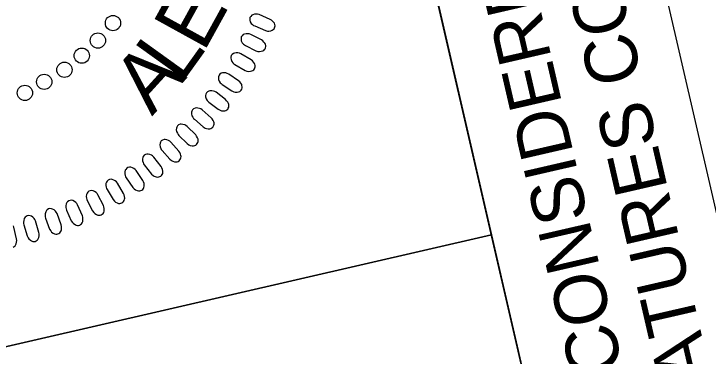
# Model space of a CAD drawing. Extents: x 480532 to 481977, y 491295 to 493182.
# Drawn here: x 480676.5 to 480749.4, y 492847.7 to 492883.6 of the extents above; entities that cross this region are included whole.
import ezdxf

# ---------------------------------------------------------------- set-up
doc = ezdxf.new("R2010")
doc.units = 0
for name, color, linetype in [('Sheet PE Seal Cell', 7, 'Continuous'), ('Sheet Plan CELL', 7, 'Continuous'), ('Sheet Sticker Exception Certification CELL', 7, 'Continuous'), ('Sheet Sticker Incomplete CELL', 7, 'Continuous')]:
    doc.layers.add(name, color=color, linetype=linetype)

msp = doc.modelspace()

# ---------------------------------------------------------------- linework, layer by layer
at = {"layer": 'Sheet PE Seal Cell'}
for points in [[(480701.799, 492882.305), (480702.928, 492881.825), (480703.144, 492881.774), (480703.293, 492881.767), (480703.494, 492881.804), (480703.633, 492881.851), (480703.75, 492881.923), (480703.827, 492882.003), (480703.89, 492882.099), (480703.915, 492882.209), (480703.934, 492882.331), (480703.921, 492882.451), (480703.869, 492882.586), (480703.82, 492882.672), (480703.708, 492882.793), (480703.566, 492882.918), (480703.428, 492883.001), (480702.275, 492883.5), (480702.11, 492883.546), (480701.964, 492883.559), (480701.782, 492883.539), (480701.609, 492883.491), (480701.498, 492883.432), (480701.381, 492883.311), (480701.304, 492883.181), (480701.283, 492883.028), (480701.288, 492882.912), (480701.329, 492882.756), (480701.439, 492882.58), (480701.578, 492882.448), (480701.686, 492882.369)], [(480700.834, 492880.255), (480701.931, 492879.705), (480702.144, 492879.64), (480702.292, 492879.624), (480702.494, 492879.648), (480702.635, 492879.686), (480702.757, 492879.75), (480702.84, 492879.826), (480702.908, 492879.918), (480702.94, 492880.026), (480702.967, 492880.147), (480702.96, 492880.267), (480702.918, 492880.406), (480702.874, 492880.495), (480702.77, 492880.622), (480702.637, 492880.756), (480702.504, 492880.848), (480701.384, 492881.417), (480701.222, 492881.473), (480701.077, 492881.495), (480700.895, 492881.487), (480700.72, 492881.45), (480700.604, 492881.398), (480700.481, 492881.285), (480700.396, 492881.16), (480700.365, 492881.009), (480700.363, 492880.892), (480700.394, 492880.734), (480700.492, 492880.552), (480700.623, 492880.41), (480700.725, 492880.326)], [(480699.723, 492878.265), (480700.783, 492877.647), (480700.991, 492877.568), (480701.138, 492877.543), (480701.341, 492877.555), (480701.485, 492877.583), (480701.61, 492877.64), (480701.697, 492877.71), (480701.771, 492877.797), (480701.81, 492877.904), (480701.844, 492878.023), (480701.846, 492878.143), (480701.812, 492878.284), (480701.773, 492878.375), (480701.678, 492878.51), (480701.553, 492878.651), (480701.426, 492878.751), (480700.344, 492879.39), (480700.187, 492879.456), (480700.043, 492879.487), (480699.86, 492879.491), (480699.684, 492879.464), (480699.566, 492879.42), (480699.435, 492879.315), (480699.342, 492879.195), (480699.301, 492879.046), (480699.292, 492878.931), (480699.313, 492878.771), (480699.4, 492878.582), (480699.521, 492878.433), (480699.618, 492878.342)], [(480698.38, 492876.174), (480699.399, 492875.491), (480699.601, 492875.4), (480699.746, 492875.365), (480699.95, 492875.364), (480700.095, 492875.384), (480700.224, 492875.432), (480700.316, 492875.497), (480700.394, 492875.579), (480700.44, 492875.684), (480700.482, 492875.8), (480700.491, 492875.919), (480700.466, 492876.062), (480700.433, 492876.156), (480700.346, 492876.296), (480700.23, 492876.445), (480700.111, 492876.553), (480699.071, 492877.258), (480698.917, 492877.334), (480698.776, 492877.374), (480698.594, 492877.389), (480698.416, 492877.374), (480698.296, 492877.337), (480698.158, 492877.24), (480698.058, 492877.127), (480698.008, 492876.981), (480697.992, 492876.866), (480698.003, 492876.705), (480698.078, 492876.511), (480698.19, 492876.355), (480698.281, 492876.259)], [(480696.994, 492874.305), (480697.968, 492873.559), (480698.164, 492873.455), (480698.307, 492873.412), (480698.51, 492873.398), (480698.656, 492873.408), (480698.787, 492873.449), (480698.883, 492873.507), (480698.967, 492873.585), (480699.019, 492873.686), (480699.068, 492873.799), (480699.084, 492873.918), (480699.068, 492874.062), (480699.042, 492874.158), (480698.964, 492874.303), (480698.857, 492874.459), (480698.745, 492874.574), (480697.751, 492875.344), (480697.603, 492875.429), (480697.465, 492875.478), (480697.284, 492875.504), (480697.105, 492875.5), (480696.982, 492875.471), (480696.839, 492875.383), (480696.733, 492875.276), (480696.674, 492875.133), (480696.65, 492875.02), (480696.651, 492874.858), (480696.713, 492874.66), (480696.815, 492874.497), (480696.9, 492874.395)], [(480695.475, 492872.515), (480696.401, 492871.709), (480696.591, 492871.593), (480696.73, 492871.54), (480696.932, 492871.514), (480697.079, 492871.515), (480697.212, 492871.548), (480697.311, 492871.6), (480697.4, 492871.672), (480697.458, 492871.769), (480697.514, 492871.879), (480697.538, 492871.998), (480697.531, 492872.142), (480697.51, 492872.24), (480697.442, 492872.389), (480697.346, 492872.551), (480697.241, 492872.673), (480696.297, 492873.503), (480696.154, 492873.598), (480696.02, 492873.656), (480695.841, 492873.693), (480695.662, 492873.7), (480695.538, 492873.679), (480695.389, 492873.6), (480695.276, 492873.5), (480695.208, 492873.361), (480695.177, 492873.25), (480695.168, 492873.088), (480695.218, 492872.887), (480695.31, 492872.718), (480695.387, 492872.611)], [(480693.838, 492870.827), (480694.711, 492869.965), (480694.893, 492869.837), (480695.029, 492869.776), (480695.229, 492869.737), (480695.375, 492869.729), (480695.511, 492869.753), (480695.612, 492869.799), (480695.705, 492869.865), (480695.77, 492869.959), (480695.832, 492870.065), (480695.864, 492870.182), (480695.866, 492870.326), (480695.851, 492870.424), (480695.792, 492870.578), (480695.706, 492870.746), (480695.609, 492870.874), (480694.72, 492871.763), (480694.584, 492871.866), (480694.452, 492871.932), (480694.276, 492871.98), (480694.098, 492871.999), (480693.973, 492871.986), (480693.82, 492871.916), (480693.701, 492871.823), (480693.624, 492871.689), (480693.586, 492871.58), (480693.568, 492871.419), (480693.604, 492871.215), (480693.685, 492871.04), (480693.756, 492870.929)], [(480692.076, 492869.234), (480692.893, 492868.319), (480693.067, 492868.181), (480693.199, 492868.111), (480693.395, 492868.059), (480693.542, 492868.042), (480693.678, 492868.057), (480693.782, 492868.097), (480693.879, 492868.157), (480693.949, 492868.247), (480694.019, 492868.349), (480694.057, 492868.463), (480694.068, 492868.607), (480694.06, 492868.706), (480694.011, 492868.863), (480693.936, 492869.036), (480693.847, 492869.171), (480693.015, 492870.113), (480692.885, 492870.224), (480692.758, 492870.298), (480692.586, 492870.358), (480692.409, 492870.387), (480692.283, 492870.382), (480692.127, 492870.322), (480692.001, 492870.237), (480691.917, 492870.108), (480691.872, 492870.001), (480691.843, 492869.842), (480691.867, 492869.636), (480691.937, 492869.457), (480692.001, 492869.341)], [(480690.217, 492867.731), (480690.975, 492866.766), (480691.14, 492866.617), (480691.268, 492866.539), (480691.461, 492866.476), (480691.605, 492866.449), (480691.743, 492866.456), (480691.849, 492866.489), (480691.95, 492866.543), (480692.025, 492866.628), (480692.101, 492866.725), (480692.146, 492866.837), (480692.167, 492866.98), (480692.165, 492867.08), (480692.125, 492867.239), (480692.061, 492867.417), (480691.98, 492867.556), (480691.21, 492868.549), (480691.087, 492868.668), (480690.966, 492868.75), (480690.797, 492868.82), (480690.622, 492868.862), (480690.496, 492868.864), (480690.336, 492868.814), (480690.206, 492868.737), (480690.114, 492868.613), (480690.062, 492868.509), (480690.023, 492868.352), (480690.035, 492868.146), (480690.092, 492867.962), (480690.149, 492867.842)], [(480688.315, 492866.369), (480689.011, 492865.359), (480689.167, 492865.199), (480689.289, 492865.114), (480689.477, 492865.038), (480689.62, 492865.003), (480689.757, 492865.001), (480689.865, 492865.027), (480689.97, 492865.074), (480690.05, 492865.154), (480690.132, 492865.247), (480690.184, 492865.355), (480690.213, 492865.497), (480690.218, 492865.596), (480690.188, 492865.758), (480690.135, 492865.939), (480690.064, 492866.084), (480689.357, 492867.123), (480689.242, 492867.25), (480689.126, 492867.339), (480688.962, 492867.42), (480688.79, 492867.471), (480688.665, 492867.482), (480688.502, 492867.442), (480688.367, 492867.373), (480688.267, 492867.256), (480688.209, 492867.155), (480688.16, 492867.001), (480688.159, 492866.794), (480688.205, 492866.608), (480688.254, 492866.484)], [(480686.306, 492865.127), (480686.937, 492864.076), (480687.082, 492863.907), (480687.198, 492863.813), (480687.382, 492863.726), (480687.522, 492863.682), (480687.659, 492863.671), (480687.769, 492863.691), (480687.875, 492863.731), (480687.961, 492863.806), (480688.048, 492863.893), (480688.107, 492863.998), (480688.145, 492864.138), (480688.156, 492864.237), (480688.137, 492864.4), (480688.095, 492864.585), (480688.033, 492864.733), (480687.393, 492865.814), (480687.286, 492865.948), (480687.176, 492866.045), (480687.017, 492866.135), (480686.849, 492866.197), (480686.724, 492866.216), (480686.559, 492866.186), (480686.42, 492866.126), (480686.313, 492866.015), (480686.249, 492865.919), (480686.191, 492865.768), (480686.176, 492865.561), (480686.21, 492865.373), (480686.252, 492865.246)], [(480684.227, 492863.977), (480684.791, 492862.888), (480684.925, 492862.71), (480685.035, 492862.61), (480685.213, 492862.511), (480685.35, 492862.458), (480685.486, 492862.439), (480685.597, 492862.452), (480685.706, 492862.486), (480685.796, 492862.555), (480685.888, 492862.636), (480685.954, 492862.737), (480686.001, 492862.874), (480686.018, 492862.973), (480686.009, 492863.136), (480685.979, 492863.323), (480685.926, 492863.475), (480685.355, 492864.595), (480685.257, 492864.735), (480685.153, 492864.838), (480685, 492864.939), (480684.837, 492865.011), (480684.714, 492865.037), (480684.546, 492865.018), (480684.404, 492864.967), (480684.29, 492864.863), (480684.22, 492864.771), (480684.153, 492864.624), (480684.125, 492864.419), (480684.147, 492864.228), (480684.181, 492864.099)], [(480682.053, 492862.984), (480682.548, 492861.861), (480682.67, 492861.675), (480682.774, 492861.569), (480682.946, 492861.459), (480683.079, 492861.397), (480683.213, 492861.37), (480683.325, 492861.375), (480683.436, 492861.402), (480683.53, 492861.466), (480683.627, 492861.541), (480683.699, 492861.638), (480683.755, 492861.772), (480683.778, 492861.869), (480683.779, 492862.033), (480683.761, 492862.221), (480683.718, 492862.376), (480683.218, 492863.529), (480683.129, 492863.675), (480683.032, 492863.785), (480682.886, 492863.895), (480682.726, 492863.978), (480682.605, 492864.012), (480682.438, 492864.003), (480682.292, 492863.961), (480682.172, 492863.864), (480682.096, 492863.777), (480682.02, 492863.634), (480681.979, 492863.431), (480681.99, 492863.239), (480682.015, 492863.109)], [(480679.862, 492862.137), (480680.285, 492860.985), (480680.396, 492860.793), (480680.493, 492860.679), (480680.657, 492860.558), (480680.786, 492860.489), (480680.919, 492860.453), (480681.03, 492860.452), (480681.143, 492860.471), (480681.241, 492860.529), (480681.343, 492860.598), (480681.421, 492860.69), (480681.484, 492860.82), (480681.513, 492860.916), (480681.525, 492861.079), (480681.519, 492861.268), (480681.485, 492861.426), (480681.059, 492862.608), (480680.98, 492862.759), (480680.889, 492862.875), (480680.75, 492862.994), (480680.597, 492863.086), (480680.478, 492863.128), (480680.31, 492863.13), (480680.163, 492863.097), (480680.036, 492863.008), (480679.955, 492862.925), (480679.87, 492862.788), (480679.816, 492862.588), (480679.815, 492862.396), (480679.832, 492862.264)], [(480677.579, 492861.442), (480677.928, 492860.265), (480678.027, 492860.066), (480678.117, 492859.947), (480678.273, 492859.816), (480678.397, 492859.738), (480678.528, 492859.694), (480678.639, 492859.686), (480678.753, 492859.699), (480678.854, 492859.75), (480678.96, 492859.813), (480679.043, 492859.9), (480679.115, 492860.025), (480679.15, 492860.119), (480679.171, 492860.281), (480679.178, 492860.471), (480679.154, 492860.629), (480678.803, 492861.837), (480678.733, 492861.993), (480678.65, 492862.113), (480678.518, 492862.241), (480678.371, 492862.343), (480678.256, 492862.392), (480678.088, 492862.405), (480677.939, 492862.381), (480677.807, 492862.3), (480677.721, 492862.222), (480677.628, 492862.09), (480677.561, 492861.894), (480677.548, 492861.702), (480677.556, 492861.57)]]:
    msp.add_lwpolyline(points, close=True, dxfattribs=at)
msp.add_lwpolyline([(480676.459, 492859.093), (480676.57, 492859.149), (480676.658, 492859.23), (480676.738, 492859.351), (480676.778, 492859.442), (480676.81, 492859.603), (480676.828, 492859.792), (480676.814, 492859.952), (480676.54, 492861.179), (480676.48, 492861.338)], dxfattribs=at)
for centre in [(480686.93, 492882.614), (480685.349, 492880.779), (480683.659, 492879.19), (480681.834, 492877.708), (480679.713, 492876.443), (480677.691, 492875.283)]:
    msp.add_circle(centre, 0.801, dxfattribs=at)
at = {"layer": 'Sheet Plan CELL'}
msp.add_line((480617.018, 492835.113), (480726.604, 492860.388), dxfattribs=at)
for points in [[(481918.067, 491698.303), (480894.93, 491462.423), (480602.878, 492729.179), (480749.103, 492762.9), (480704.18, 492957.828), (481581.119, 493159.981)], [(480617.018, 492835.113), (480594.546, 492932.542), (480704.18, 492957.828), (480726.655, 492860.387)], [(480639.493, 492737.62), (480617.018, 492835.113), (480726.655, 492860.387), (480749.103, 492762.9)]]:
    msp.add_lwpolyline(points, close=True, dxfattribs=at)
at = {"layer": 'Sheet Sticker Exception Certification CELL'}
for p, q in [((480727.068, 492963.104), (480772.002, 492768.179)), ((480727.068, 492963.104), (480772.002, 492768.179)), ((480749.103, 492762.9), (480704.168, 492957.825)), ((480749.103, 492762.9), (480704.168, 492957.825))]:
    msp.add_line(p, q, dxfattribs=at)

# ---------------------------------------------------------------- texts
at = {"layer": 'Sheet PE Seal Cell'}
for s, rotation, p in [('E', 61.12989, (480696.431, 492879.439)), ('L', 54.28424, (480694.038, 492876.103)), ('A', 47.66457, (480691.022, 492872.801))]:
    msp.add_text(s, height=6.236, rotation=rotation, dxfattribs=at).set_placement(p)
at = {"layer": 'Sheet Sticker Exception Certification CELL'}
for s, p in [('UNLESS ALL SIGNATURES COMPLETED', (480764.165, 492782.792)), ('UNLESS ALL SIGNATURES COMPLETED', (480764.165, 492782.792)), ('DOCUMENT NOT CONSIDERED FINAL', (480754.45, 492785.756)), ('DOCUMENT NOT CONSIDERED FINAL', (480754.45, 492785.756))]:
    msp.add_text(s, height=5.5, rotation=102.98112, dxfattribs=at).set_placement(p)
at = {"layer": 'Sheet Sticker Incomplete CELL'}
msp.add_text('DO NOT USE FOR R/W ACQUISITION', height=5.76, rotation=102.98112, dxfattribs=at).set_placement((480680.972, 492786.948))

doc.saveas('drawing.dxf')
